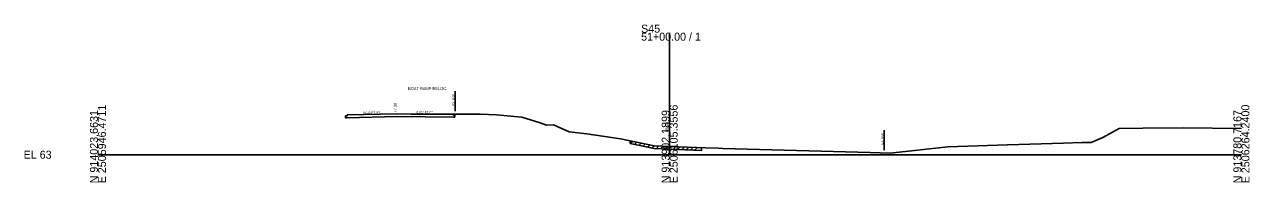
# Model space of a CAD drawing. Extents: x -26 to 403, y -10 to 17520.
# Drawn here: x -25.7 to 402.8, y 12490.3 to 12545.5 of the extents above; entities that cross this region are included whole.
import ezdxf

# ---------------------------------------------------------------- set-up
doc = ezdxf.new("R2010")
doc.units = 0
for name, color, linetype in [('RD_GPK_XS_Cell', 7, 'Continuous'), ('RD_Sketch9', 7, 'Continuous'), ('RD_XS_ExGround', 7, 'Continuous'), ('RD_XS_ExPaveRet', 7, 'Continuous'), ('RD_XS_ExRW', 7, 'Continuous'), ('RD_XS_TX_Elev_EX', 7, 'Continuous')]:
    doc.layers.add(name, color=color, linetype=linetype)

msp = doc.modelspace()

# ---------------------------------------------------------------- linework, layer by layer
at = {"layer": 'RD_GPK_XS_Cell'}
for p, q in [((200, 12500), (200, 12542.62)), ((0, 12500), (200, 12500)), ((200, 12500), (400, 12500))]:
    msp.add_line(p, q, dxfattribs=at)
at = {"layer": 'RD_Sketch9'}
for p, q in [((86.64, 12513.57), (87.14, 12513.58)), ((86.64, 12512.9), (86.64, 12513.57)), ((104.51, 12514.3), (87.14, 12513.91)), ((87.14, 12513.58), (87.14, 12513.91)), ((87.14, 12512.91), (104.51, 12513.3)), ((104.51, 12514.3), (124.4, 12514.15)), ((104.51, 12513.3), (124.4, 12513.15)), ((124.4, 12513.82), (124.4, 12514.15)), ((124.9, 12513.82), (124.4, 12513.82)), ((124.4, 12513.15), (124.9, 12513.15)), ((124.9, 12513.15), (124.9, 12513.82)), ((87.14, 12512.91), (86.64, 12512.9))]:
    msp.add_line(p, q, dxfattribs=at)
at = {"layer": 'RD_XS_ExGround'}
for p, q in [((109.63, 12514.19), (112.4, 12514.19)), ((112.4, 12514.19), (120.37, 12514.21)), ((120.37, 12514.21), (133.87, 12514.17)), ((133.87, 12514.17), (139.4, 12513.91)), ((139.4, 12513.91), (148.26, 12513.11)), ((148.26, 12513.11), (154.66, 12511.1)), ((154.66, 12511.1), (156.87, 12510.33)), ((156.87, 12510.33), (159.42, 12510.39)), ((159.42, 12510.39), (164.83, 12507.98)), ((351.52, 12505.97), (357.23, 12509.19)), ((357.23, 12509.19), (365.58, 12509.27)), ((365.58, 12509.27), (379.58, 12509.39)), ((379.58, 12509.39), (400, 12509.17)), ((164.83, 12507.98), (170.97, 12507.3)), ((170.97, 12507.3), (182.8, 12505.6)), ((182.8, 12505.6), (194.55, 12503.13)), ((347.48, 12504.25), (351.52, 12505.97)), ((194.55, 12503.13), (200, 12502.92)), ((200, 12502.92), (212.49, 12502.44)), ((212.49, 12502.44), (216.92, 12502.27)), ((216.92, 12502.27), (218.57, 12502.17)), ((218.57, 12502.17), (270.1, 12500.77)), ((270.1, 12500.77), (277.13, 12500.52)), ((277.13, 12500.52), (297.35, 12502.76)), ((297.35, 12502.76), (318.13, 12503.4)), ((318.13, 12503.4), (337.74, 12504.01)), ((337.74, 12504.01), (344.17, 12504.29)), ((344.17, 12504.29), (347.48, 12504.25))]:
    msp.add_line(p, q, dxfattribs=at)
at = {"layer": 'RD_XS_ExPaveRet'}
for p, q in [((186.24, 12503.87), (186.24, 12504.87)), ((186.24, 12503.87), (187.07, 12504.7)), ((186.24, 12503.87), (194.55, 12502.13)), ((187.74, 12503.56), (188.57, 12504.38)), ((189.24, 12503.24), (190.07, 12504.07)), ((190.74, 12502.93), (191.57, 12503.75)), ((192.24, 12502.61), (193.07, 12503.44)), ((193.74, 12502.29), (194.57, 12503.12)), ((194.55, 12502.13), (200, 12501.92)), ((195.24, 12502.1), (196.21, 12503.06)), ((196.74, 12502.04), (197.71, 12503)), ((198.24, 12501.98), (199.21, 12502.95)), ((199.74, 12501.93), (200.71, 12502.89)), ((200, 12501.92), (211.14, 12501.49)), ((201.24, 12501.87), (202.21, 12502.83)), ((202.74, 12501.81), (203.71, 12502.77)), ((204.24, 12501.75), (205.21, 12502.72)), ((205.74, 12501.7), (206.71, 12502.66)), ((207.24, 12501.64), (208.21, 12502.6)), ((208.74, 12501.58), (209.71, 12502.55)), ((211.14, 12502.49), (211.14, 12501.49))]:
    msp.add_line(p, q, dxfattribs=at)
at = {"layer": 'RD_XS_ExRW'}
for p, q in [((125, 12515.2), (125, 12522.2)), ((275, 12501.6), (275, 12508.6))]:
    msp.add_line(p, q, dxfattribs=at)

# ---------------------------------------------------------------- texts
at = {"layer": 'RD_GPK_XS_Cell'}
for s, p in [('S45', (190, 12542.62)), ('51+00.00 / 1', (190, 12539.82)), ('EL 63', (-26, 12498.6))]:
    msp.add_text(s, height=2.8, dxfattribs=at).set_placement(p)
for s, p in [('N 914023.6631', (0, 12490)), ('E 2505946.4711', (2.8, 12490)), ('N 913902.1899', (200, 12490)), ('E 2506105.3556', (202.8, 12490)), ('N 913780.7167', (400, 12490)), ('E 2506264.2400', (402.8, 12490))]:
    msp.add_text(s, height=2.8, rotation=90, dxfattribs=at).set_placement(p)
at = {"layer": 'RD_Sketch9'}
msp.add_text('BOAT RAMP RELOC.', height=1, dxfattribs=at).set_placement((108.52, 12522.59))
for s, height, rotation, p in [(' 77.30', 1, 90, (104.51, 12514.3)), ('0.023 FT./FT.', 0.75, 1.3007, (92.79, 12514.29)), ('0.007 FT./FT.', 0.75, 359.5782, (111.43, 12514.5))]:
    msp.add_text(s, height=height, rotation=rotation, dxfattribs=at).set_placement(p)
at = {"layer": 'RD_XS_ExRW'}
for p in [(124.75, 12517.15), (274.75, 12503.55)]:
    msp.add_text('EX. R/W ', height=0.75, rotation=90, dxfattribs=at).set_placement(p)
at = {"layer": 'RD_XS_TX_Elev_EX'}
msp.add_text('65.92', height=1, rotation=90, dxfattribs=at).set_placement((199.5, 12507.92))

doc.saveas('drawing.dxf')
